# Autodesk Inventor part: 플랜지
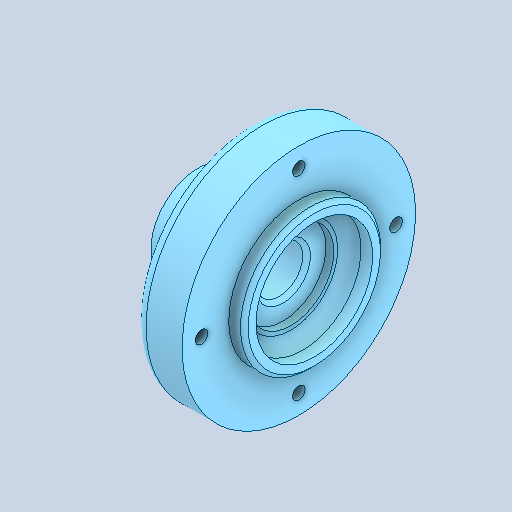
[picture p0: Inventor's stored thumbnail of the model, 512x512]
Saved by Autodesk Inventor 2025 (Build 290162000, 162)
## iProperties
Created: 2026-03
Part Number: 플랜지
Material: 강철, 연강
Document SubType Name: Modeling
Designer: KDI
Density: 7.85 g/cm^3
Appearance: 기본값
Author: jhkim
Sending System: Autodesk Inventor 2026
Preprocessor: ST-DEVELOPER v20.1
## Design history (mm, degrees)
feature "솔리드1"
node "솔리드2"
